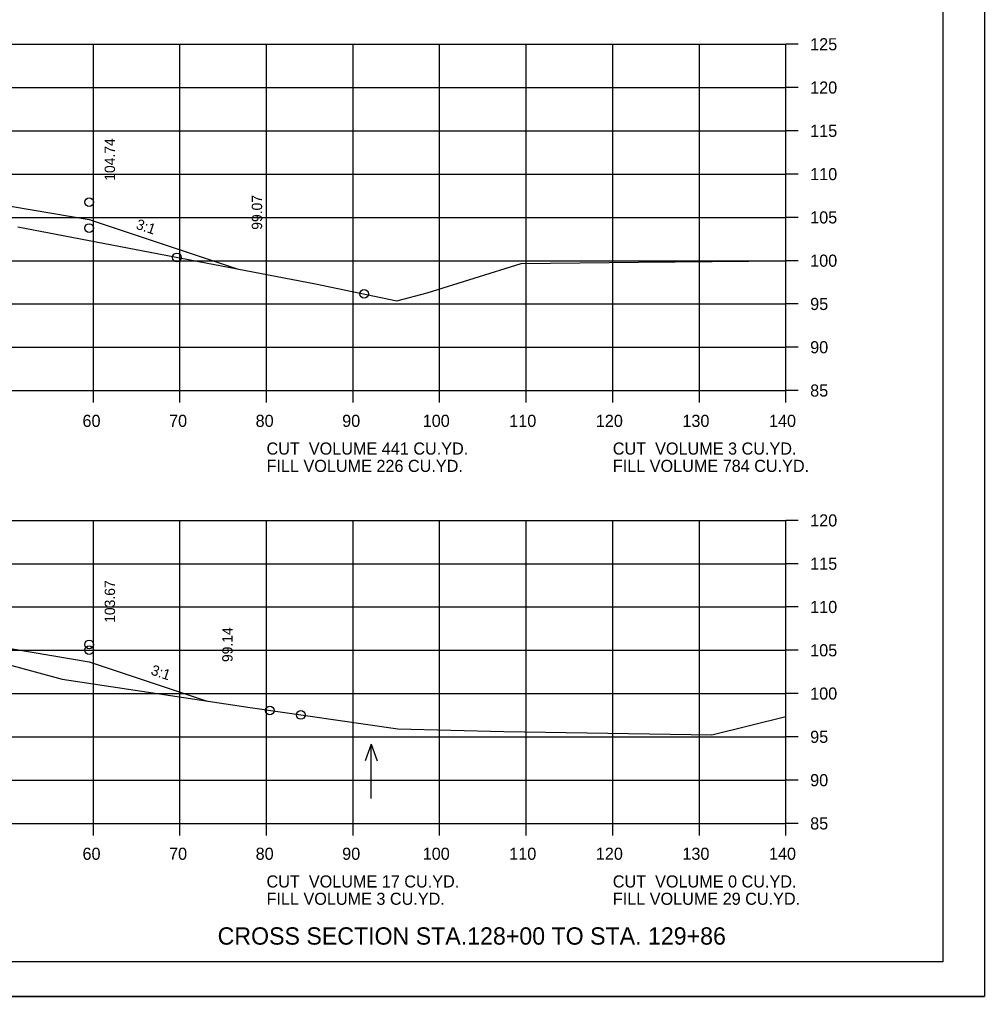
# Model space of a CAD drawing. Extents: x 1175611 to 1176402, y -433344 to -416213.
# Drawn here: x 1175832.4 to 1175943.9, y -430996.8 to -430884 of the extents above; entities that cross this region are included whole.
import ezdxf

# ---------------------------------------------------------------- set-up
doc = ezdxf.new("R2010")
doc.units = 0
for name, color, linetype in [('Default', 7, 'Continuous'), ('R_Axis', 7, 'Continuous'), ('R_Axis Annot', 7, 'Continuous'), ('R_Border', 7, 'Continuous'), ('R_Draft', 7, 'Continuous'), ('R_Exist Surface', 7, 'Continuous'), ('R_Fin Surface', 7, 'Continuous'), ('R_Grid', 7, 'Continuous'), ('R_No Plot', 7, 'Continuous'), ('R_Water Annot', 7, 'Continuous'), ('R_Xsect Elev', 7, 'Continuous'), ('R_Xsect Slope', 7, 'Continuous')]:
    doc.layers.add(name, color=color, linetype=linetype)

msp = doc.modelspace()

# ---------------------------------------------------------------- linework, layer by layer
at = {"layer": 'R_Axis'}
for p, q in [((1175920.97, -430926.83), (1175920.97, -430886.83)), ((1175922.37, -430886.83), (1175920.97, -430886.83)), ((1175922.37, -430891.83), (1175920.97, -430891.83)), ((1175922.37, -430896.83), (1175920.97, -430896.83)), ((1175922.37, -430901.83), (1175920.97, -430901.83)), ((1175922.37, -430906.83), (1175920.97, -430906.83)), ((1175922.37, -430911.83), (1175920.97, -430911.83)), ((1175922.37, -430916.83), (1175920.97, -430916.83)), ((1175922.37, -430921.83), (1175920.97, -430921.83)), ((1175640.97, -430926.83), (1175920.97, -430926.83)), ((1175840.97, -430928.23), (1175840.97, -430926.83)), ((1175850.97, -430928.23), (1175850.97, -430926.83)), ((1175860.97, -430928.23), (1175860.97, -430926.83)), ((1175870.97, -430928.23), (1175870.97, -430926.83)), ((1175880.97, -430928.23), (1175880.97, -430926.83)), ((1175890.97, -430928.23), (1175890.97, -430926.83)), ((1175900.97, -430928.23), (1175900.97, -430926.83)), ((1175910.97, -430928.23), (1175910.97, -430926.83)), ((1175920.97, -430928.23), (1175920.97, -430926.83)), ((1175922.37, -430926.83), (1175920.97, -430926.83)), ((1175920.97, -430976.83), (1175920.97, -430941.83)), ((1175922.37, -430941.83), (1175920.97, -430941.83)), ((1175922.37, -430946.83), (1175920.97, -430946.83)), ((1175922.37, -430951.83), (1175920.97, -430951.83)), ((1175922.37, -430956.83), (1175920.97, -430956.83)), ((1175922.37, -430961.83), (1175920.97, -430961.83)), ((1175922.37, -430966.83), (1175920.97, -430966.83)), ((1175922.37, -430971.83), (1175920.97, -430971.83)), ((1175640.97, -430976.83), (1175920.97, -430976.83)), ((1175840.97, -430978.23), (1175840.97, -430976.83)), ((1175850.97, -430978.23), (1175850.97, -430976.83)), ((1175860.97, -430978.23), (1175860.97, -430976.83)), ((1175870.97, -430978.23), (1175870.97, -430976.83)), ((1175880.97, -430978.23), (1175880.97, -430976.83)), ((1175890.97, -430978.23), (1175890.97, -430976.83)), ((1175900.97, -430978.23), (1175900.97, -430976.83)), ((1175910.97, -430978.23), (1175910.97, -430976.83)), ((1175920.97, -430978.23), (1175920.97, -430976.83)), ((1175922.37, -430976.83), (1175920.97, -430976.83))]:
    msp.add_line(p, q, dxfattribs=at)
at = {"layer": 'R_Border'}
for q in [(1175939.15, -430787.37), (1175622.97, -430992.83)]:
    msp.add_line((1175939.15, -430992.83), q, dxfattribs=at)
at = {"layer": 'R_Exist Surface'}
for points in [[(1175832.24, -430907.92), (1175866.63, -430914.52), (1175876.01, -430916.45), (1175879.53, -430915.56), (1175890.4, -430912.15), (1175903.94, -430912), (1175920.97, -430911.86)], [(1175826.69, -430957.29), (1175837.36, -430960.16), (1175859.08, -430963.45), (1175876.15, -430965.92), (1175888.37, -430966.23), (1175912.43, -430966.59), (1175920.97, -430964.48)]]:
    msp.add_lwpolyline(points, dxfattribs=at)
at = {"layer": 'R_Fin Surface'}
for points in [[(1175696.36, -430905.55), (1175720.1, -430913.46), (1175721.47, -430913.01), (1175728.25, -430911.88), (1175743.47, -430909.34), (1175749.47, -430908.86), (1175751.47, -430908.7), (1175780.97, -430906.37), (1175810.47, -430904.03), (1175812.47, -430903.87), (1175818.47, -430903.4), (1175831.62, -430905.59), (1175840.47, -430907.06), (1175857.71, -430912.81)], [(1175696.36, -430905.55), (1175720.1, -430913.46), (1175721.47, -430913.01), (1175728.25, -430911.88), (1175743.47, -430909.34), (1175749.47, -430908.86), (1175751.47, -430908.7), (1175780.97, -430906.37), (1175810.47, -430904.03), (1175812.47, -430903.87), (1175818.47, -430903.4), (1175831.62, -430905.59), (1175840.47, -430907.06), (1175857.71, -430912.81)], [(1175694.12, -430955.65), (1175720.46, -430964.43), (1175721.47, -430964.1), (1175728.25, -430962.97), (1175743.47, -430960.43), (1175749.47, -430959.95), (1175751.47, -430959.79), (1175780.97, -430957.46), (1175810.47, -430955.12), (1175812.47, -430954.96), (1175818.47, -430954.49), (1175831.62, -430956.68), (1175840.47, -430958.15), (1175854.12, -430962.7)], [(1175694.12, -430955.65), (1175720.46, -430964.43), (1175721.47, -430964.1), (1175728.25, -430962.97), (1175743.47, -430960.43), (1175749.47, -430959.95), (1175751.47, -430959.79), (1175780.97, -430957.46), (1175810.47, -430955.12), (1175812.47, -430954.96), (1175818.47, -430954.49), (1175831.62, -430956.68), (1175840.47, -430958.15), (1175854.12, -430962.7)]]:
    msp.add_lwpolyline(points, dxfattribs=at)
at = {"layer": 'R_Grid'}
for p, q in [((1175640.97, -430886.83), (1175920.97, -430886.83)), ((1175840.97, -430926.83), (1175840.97, -430886.83)), ((1175850.97, -430926.83), (1175850.97, -430886.83)), ((1175860.97, -430926.83), (1175860.97, -430886.83)), ((1175870.97, -430926.83), (1175870.97, -430886.83)), ((1175880.97, -430926.83), (1175880.97, -430886.83)), ((1175890.97, -430926.83), (1175890.97, -430886.83)), ((1175900.97, -430926.83), (1175900.97, -430886.83)), ((1175910.97, -430926.83), (1175910.97, -430886.83)), ((1175920.97, -430926.83), (1175920.97, -430886.83)), ((1175640.97, -430891.83), (1175920.97, -430891.83)), ((1175640.97, -430896.83), (1175920.97, -430896.83)), ((1175640.97, -430901.83), (1175920.97, -430901.83)), ((1175640.97, -430906.83), (1175920.97, -430906.83)), ((1175640.97, -430911.83), (1175920.97, -430911.83)), ((1175640.97, -430916.83), (1175920.97, -430916.83)), ((1175640.97, -430921.83), (1175920.97, -430921.83)), ((1175640.97, -430926.83), (1175920.97, -430926.83)), ((1175640.97, -430941.83), (1175920.97, -430941.83)), ((1175840.97, -430976.83), (1175840.97, -430941.83)), ((1175850.97, -430976.83), (1175850.97, -430941.83)), ((1175860.97, -430976.83), (1175860.97, -430941.83)), ((1175870.97, -430976.83), (1175870.97, -430941.83)), ((1175880.97, -430976.83), (1175880.97, -430941.83)), ((1175890.97, -430976.83), (1175890.97, -430941.83)), ((1175900.97, -430976.83), (1175900.97, -430941.83)), ((1175910.97, -430976.83), (1175910.97, -430941.83)), ((1175920.97, -430976.83), (1175920.97, -430941.83)), ((1175640.97, -430946.83), (1175920.97, -430946.83)), ((1175640.97, -430951.83), (1175920.97, -430951.83)), ((1175640.97, -430956.83), (1175920.97, -430956.83)), ((1175640.97, -430961.83), (1175920.97, -430961.83)), ((1175640.97, -430966.83), (1175920.97, -430966.83)), ((1175640.97, -430971.83), (1175920.97, -430971.83)), ((1175640.97, -430976.83), (1175920.97, -430976.83))]:
    msp.add_line(p, q, dxfattribs=at)
at = {"layer": 'R_No Plot'}
msp.add_line((1175610.57, -430996.81), (1175943.91, -430996.81), dxfattribs=at)
msp.add_lwpolyline([(1175610.57, -430783.48), (1175943.91, -430783.48), (1175943.91, -430996.82), (1175610.57, -430996.82)], close=True, dxfattribs=at)
for centre in [(1175840.47, -430905.08), (1175840.47, -430908.06), (1175850.62, -430911.45), (1175850.62, -430911.45), (1175872.25, -430915.67), (1175840.47, -430956.15), (1175840.47, -430956.82), (1175861.36, -430963.78), (1175861.36, -430963.78), (1175864.93, -430964.3)]:
    msp.add_circle(centre, 0.5, dxfattribs=at)
at = {"layer": 'R_Water Annot'}
for p, q in [((1175873.06, -430967.66), (1175872.36, -430969.59)), ((1175873.06, -430973.95), (1175873.06, -430967.66)), ((1175873.06, -430967.66), (1175873.76, -430969.59))]:
    msp.add_line(p, q, dxfattribs=at)

# ---------------------------------------------------------------- texts
at = {"layer": 'Default'}
for s, p in [('CUT  VOLUME 441 CU.YD.', (1175860.97, -430934.23)), ('CUT  VOLUME 3 CU.YD.', (1175900.97, -430934.23)), ('FILL VOLUME 226 CU.YD.', (1175860.97, -430936.23)), ('FILL VOLUME 784 CU.YD.', (1175900.97, -430936.23)), ('CUT  VOLUME 17 CU.YD.', (1175860.97, -430984.23)), ('CUT  VOLUME 0 CU.YD.', (1175900.97, -430984.23)), ('FILL VOLUME 3 CU.YD.', (1175860.97, -430986.23)), ('FILL VOLUME 29 CU.YD.', (1175900.97, -430986.23))]:
    msp.add_text(s, height=1.4, dxfattribs=at).set_placement(p)
at = {"layer": 'R_Axis Annot'}
for s, p in [('125', (1175923.77, -430887.53)), ('120', (1175923.77, -430892.53)), ('115', (1175923.77, -430897.53)), ('110', (1175923.77, -430902.53)), ('105', (1175923.77, -430907.53)), ('100', (1175923.77, -430912.53)), ('95', (1175923.77, -430917.53)), ('90', (1175923.77, -430922.53)), ('85', (1175923.77, -430927.53)), ('60', (1175839.71, -430931.03)), ('70', (1175849.71, -430931.03)), ('80', (1175859.71, -430931.03)), ('90', (1175869.71, -430931.03)), ('100', (1175879.01, -430931.03)), ('110', (1175889.01, -430931.03)), ('120', (1175899.01, -430931.03)), ('130', (1175909.01, -430931.03)), ('140', (1175919.01, -430931.03)), ('120', (1175923.77, -430942.53)), ('115', (1175923.77, -430947.53)), ('110', (1175923.77, -430952.53)), ('105', (1175923.77, -430957.53)), ('100', (1175923.77, -430962.53)), ('95', (1175923.77, -430967.53)), ('90', (1175923.77, -430972.53)), ('85', (1175923.77, -430977.53)), ('60', (1175839.71, -430981.03)), ('70', (1175849.71, -430981.03)), ('80', (1175859.71, -430981.03)), ('90', (1175869.71, -430981.03)), ('100', (1175879.01, -430981.03)), ('110', (1175889.01, -430981.03)), ('120', (1175899.01, -430981.03)), ('130', (1175909.01, -430981.03)), ('140', (1175919.01, -430981.03))]:
    msp.add_text(s, height=1.4, dxfattribs=at).set_placement(p)
at = {"layer": 'R_Draft'}
msp.add_text('CROSS SECTION STA.128+00 TO STA. 129+86', height=2, dxfattribs=at).set_placement((1175855.32, -430990.83))
at = {"layer": 'R_Xsect Elev'}
for s, p in [('104.74', (1175843.47, -430902.6)), ('99.07', (1175860.46, -430908.26)), ('103.67', (1175843.47, -430953.66)), ('99.14', (1175857.05, -430958.19))]:
    msp.add_text(s, height=1.2, rotation=90, dxfattribs=at).set_placement(p)
at = {"layer": 'R_Xsect Slope'}
for p in [(1175845.8, -430908.12), (1175847.52, -430959.61)]:
    msp.add_text('3:1', height=1.2, rotation=341.5651, dxfattribs=at).set_placement(p)

doc.saveas('drawing.dxf')
